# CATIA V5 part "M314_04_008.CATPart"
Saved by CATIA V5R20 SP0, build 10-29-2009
Part number: M314_04_008
Source: Unknown
Property "ARTICLENO": "M314-04-008"
Property "B": "35.000"
Property "BOMINFO": "M314-04-008"
Property "CODE": "M314-04-008"
Property "D": "8.000"
Property "FINALFORCE": "78.4 (8)"
Property "INITIALFORCE": "14.7 (1.5)"
Property "K": "15.000"
Property "L": "60.000"
Property "LINA": "M314-04-008"
Property "M": "M16x2.0"
Property "NB": "M314-04-008"
Property "NBSYN": "$CODE."
Property "NN": "M314-04"
Property "NT": "Spring Plunger"
Property "SUPPLIER": "CF"
Property "SW": "5.000"
Bounding box of the stored display mesh (mm): x -8 to 8, y 0 to 75, z -8 to 8
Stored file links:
  C:\Users\Utente\Desktop\3D files M314\M314_04_008.CATPart
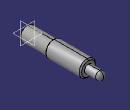
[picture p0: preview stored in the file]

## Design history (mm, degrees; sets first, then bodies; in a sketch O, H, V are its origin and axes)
Body1 "Geometry.1" (main body)
  Solid1 "M314_04_008.catpart": solid without history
